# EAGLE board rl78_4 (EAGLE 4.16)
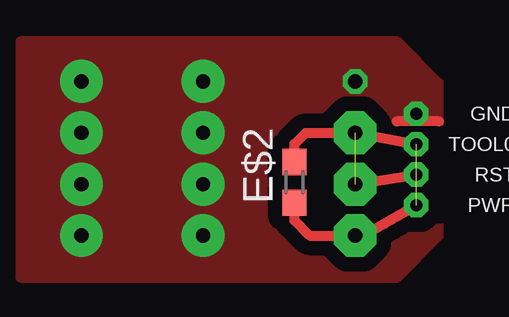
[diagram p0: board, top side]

No outline drawn. Coordinates in mm, seen from the top.
Copper layers (1*16): Top 0.035mm / dielectric 1.5mm / Bottom 0.035mm
Design rules "default": minimum track width 10mil, minimum drill 24mil, track to track 8mil, track to pad 8mil, pad to pad 8mil, via to via 8mil, smd to smd 8mil, copper to edge 40mil, drill to drill 8mil, minimum pad ring 10mil, minimum via ring 8mil, stop-mask expansion 4mil, vias tented up to drill 0mil, thermal gap 10mil
tRestrict: 2 lines

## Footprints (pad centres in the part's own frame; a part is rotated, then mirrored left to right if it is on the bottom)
R0603 = smd 1.1 x 1: 1 -0.85,0; 2 0.85,0

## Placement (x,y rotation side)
E$2  [R0603]  11.43,3.97 90 top

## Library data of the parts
E$2 = ref-packages

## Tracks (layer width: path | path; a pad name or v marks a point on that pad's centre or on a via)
GND  (via drill 0.5 pad 1.02, 0.6 pad 1.02, 0.6 pad 1.78)
  Top 0.406: 17.46,6.51 15.7,6.51
  other vias: 16.51,6.83 13.97,8.18 7.62,8.18 7.62,6.03 7.62,3.89 7.62,1.75 2.54,8.18 2.54,6.03 2.54,3.89 2.54,1.75
  pour Top (isolate 0.61): 0,9.84 0,0 15.72,0 17.46,1.75 17.46,8.1 15.72,9.84
S$1
  Top 0.406: 16.51,3.02 14.29,1.75 12.06,1.75 11.43,2.38 11.43,3.02
S$2  (via drill 0.5 pad 1.02)  (1 unrouted)
  other vias: 16.51,5.56 16.51,3.02
S$3  (via drill 0.5 pad 1.02)
  other vias: 16.51,4.29
S$4  (via drill 0.6 pad 1.78)  (1 unrouted)
  other vias: 13.97,3.89 13.97,6.03
S$5
  Top 0.406: 11.43,4.92 11.43,5.56 11.91,6.03 13.97,6.03
S$6
  Top 0.406: 13.97,6.03 16.51,5.56
S$7
  Top 0.406: 13.97,3.89 16.51,4.29
S$8  (via drill 0.6 pad 1.78)
  other vias: 13.97,1.75

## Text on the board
tPlace: GND | TOOL0 | RST | PWR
